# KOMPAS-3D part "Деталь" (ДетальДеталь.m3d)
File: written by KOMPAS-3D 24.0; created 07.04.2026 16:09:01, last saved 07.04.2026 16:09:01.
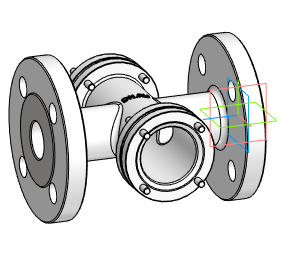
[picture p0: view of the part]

Document properties: Автор: Main; Полное имя файла: D:\DN.ru Аутсерс\Стекло смотровое DN.ru\Исходники\Стекло смотровое DN.ru SG2-34G-F тип В ГОСТ 21836-2021 Ду32 Ру40, углеродистая сталь, фланцевое\ДетальДеталь.m3d

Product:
- Body: Твердое тело1  | qty 1
- Part/product: Деталь
    additional columns: Типовые

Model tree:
1. Твердое тело1  (labels: Твердое тело1)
